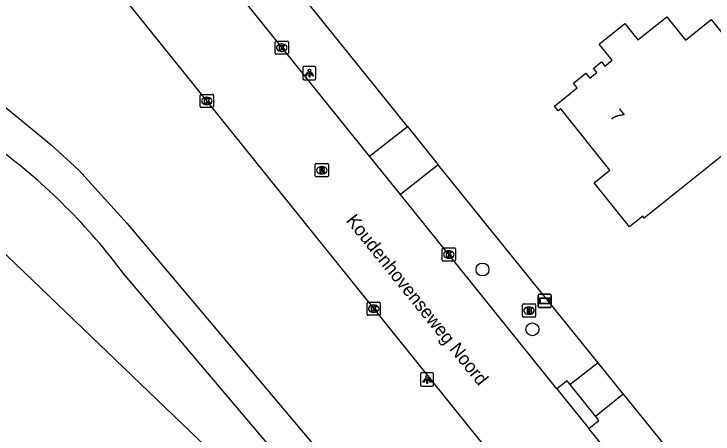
# Model space of a CAD drawing. Extents: x 162417 to 163721, y 384268 to 385416.
# Drawn here: x 163405.6 to 163458.5, y 384837.4 to 384869.2 of the extents above; entities that cross this region are included whole.
import ezdxf

# ---------------------------------------------------------------- set-up
doc = ezdxf.new("R2010")
doc.units = 0
for name, color, linetype in [('IMGEO_Berm_groen', 7, 'Continuous'), ('IMGEO_Boom', 7, 'Continuous'), ('IMGEO_Brandkraan', 7, 'Continuous'), ('IMGEO_Kolk', 7, 'Continuous'), ('IMGEO_Lichtpunt', 7, 'Continuous'), ('IMGEO_Loofbos', 7, 'Continuous'), ('IMGEO_Openbare_ruimte_label', 7, 'Continuous'), ('IMGEO_Pand', 7, 'Continuous'), ('IMGEO_Pand_nummerreeks', 7, 'Continuous'), ('IMGEO_Rijbaan_lokaal_gesloten', 7, 'Continuous'), ('IMGEO_Rioolput', 7, 'Continuous'), ('IMGEO_Verklikker', 7, 'Continuous'), ('IMGEO_Voetpad_open', 7, 'Continuous')]:
    doc.layers.add(name, color=color, linetype=linetype)

msp = doc.modelspace()

# ---------------------------------------------------------------- linework, layer by layer
at = {"layer": 'IMGEO_Berm_groen'}
for points in [[(163435.391, 384860.693), (163416.764, 384883.847)], [(163449.843, 384842.786), (163449.614, 384843.069), (163437.735, 384857.778)], [(163461.716, 384828.124), (163452.011, 384840.109), (163451.746, 384840.437)]]:
    msp.add_lwpolyline(points, dxfattribs=at)
at = {"layer": 'IMGEO_Boom'}
for centre in [(163441.083, 384849.86), (163444.862, 384845.327)]:
    msp.add_circle(centre, 0.489, dxfattribs=at)
at = {"layer": 'IMGEO_Brandkraan'}
for p, q in [((163444.106, 384846.323), (163444.106, 384847.175)), ((163444.181, 384847.249), (163445.033, 384847.249)), ((163444.594, 384847.029), (163444.619, 384847.029)), ((163445.107, 384847.175), (163445.107, 384846.323)), ((163444.617, 384846.469), (163444.592, 384846.469)), ((163445.033, 384846.249), (163444.181, 384846.249))]:
    msp.add_line(p, q, dxfattribs=at)
for points in [[(163444.106, 384846.323), (163444.106, 384847.175)], [(163444.181, 384847.249), (163445.033, 384847.249)], [(163445.107, 384847.175), (163445.107, 384846.323)], [(163444.454, 384846.949), (163444.454, 384846.549), (163444.667, 384846.549)], [(163444.685, 384846.949), (163444.454, 384846.949)], [(163444.633, 384846.868), (163444.579, 384846.868), (163444.579, 384846.792)], [(163444.579, 384846.792), (163444.632, 384846.792)], [(163444.641, 384846.716), (163444.579, 384846.716), (163444.579, 384846.635)], [(163444.579, 384846.635), (163444.641, 384846.635)], [(163445.033, 384846.249), (163444.181, 384846.249)]]:
    msp.add_lwpolyline(points, dxfattribs=at)
for centre, radius, start, end in [((163444.183, 384847.173), 0.0765, 91.552, 178.448), ((163444.183, 384847.173), 0.0765, 91.552, 178.448), ((163445.031, 384847.173), 0.0765, 1.552, 88.448), ((163445.031, 384847.173), 0.0765, 1.552, 88.448), ((163444.634, 384846.83), 0.0379, 267.8285, 90.9355), ((163444.642, 384846.675), 0.0404, 269.8759, 90.5077), ((163444.673, 384846.8), 0.251, 268.6676, 293.5347), ((163444.689, 384846.804), 0.145, 59.4692, 91.5367), ((163444.714, 384846.851), 0.0922, 285.5137, 58.1501), ((163444.719, 384846.659), 0.105, 301.3115, 78.989), ((163444.183, 384846.325), 0.0765, 181.552, 268.448), ((163444.183, 384846.325), 0.0765, 181.552, 268.448), ((163445.031, 384846.325), 0.0765, 271.552, 358.448), ((163445.031, 384846.325), 0.0765, 271.552, 358.448)]:
    msp.add_arc(centre, radius, start, end, dxfattribs=at)
for centre, major_axis, ratio, start_param, end_param in [((163444.593, 384846.749), (-0.387, 0.002), 0.722429, 4.712389, 7.853982), ((163444.618, 384846.749), (-0.39, 0.002), 0.717154, 1.570796, 4.712389)]:
    msp.add_ellipse(centre, major_axis=major_axis, ratio=ratio, start_param=start_param, end_param=end_param, dxfattribs=at)
at = {"layer": 'IMGEO_Kolk'}
for p, q in [((163425.375, 384866.238), (163425.375, 384867.09)), ((163425.45, 384867.164), (163426.302, 384867.164)), ((163426.376, 384867.09), (163426.376, 384866.238)), ((163425.863, 384866.944), (163425.888, 384866.944)), ((163426.302, 384866.164), (163425.45, 384866.164)), ((163425.886, 384866.384), (163425.861, 384866.384)), ((163419.7, 384862.2), (163419.7, 384863.052)), ((163419.775, 384863.126), (163420.627, 384863.126)), ((163420.188, 384862.906), (163420.213, 384862.906)), ((163420.701, 384863.052), (163420.701, 384862.2)), ((163420.211, 384862.346), (163420.186, 384862.346)), ((163420.627, 384862.126), (163419.775, 384862.126)), ((163438.029, 384850.568), (163438.029, 384851.42)), ((163438.104, 384851.494), (163438.956, 384851.494)), ((163438.517, 384851.274), (163438.542, 384851.274)), ((163439.03, 384851.42), (163439.03, 384850.568)), ((163438.54, 384850.714), (163438.515, 384850.714)), ((163438.956, 384850.494), (163438.104, 384850.494)), ((163432.342, 384846.464), (163432.342, 384847.316)), ((163432.417, 384847.39), (163433.269, 384847.39)), ((163432.83, 384847.17), (163432.855, 384847.17)), ((163433.343, 384847.316), (163433.343, 384846.464)), ((163432.853, 384846.61), (163432.828, 384846.61)), ((163433.269, 384846.39), (163432.417, 384846.39))]:
    msp.add_line(p, q, dxfattribs=at)
for points in [[(163425.375, 384866.238), (163425.375, 384867.09)], [(163425.45, 384867.164), (163426.302, 384867.164)], [(163426.376, 384867.09), (163426.376, 384866.238)], [(163425.696, 384866.864), (163425.819, 384866.864), (163425.819, 384866.713), (163425.949, 384866.864), (163426.113, 384866.864), (163425.967, 384866.713), (163426.12, 384866.464), (163425.968, 384866.464), (163425.883, 384866.628), (163425.819, 384866.561), (163425.819, 384866.464), (163425.696, 384866.464), (163425.696, 384866.864)], [(163426.302, 384866.164), (163425.45, 384866.164)], [(163419.7, 384862.2), (163419.7, 384863.052)], [(163419.775, 384863.126), (163420.627, 384863.126)], [(163420.701, 384863.052), (163420.701, 384862.2)], [(163420.021, 384862.826), (163420.144, 384862.826), (163420.144, 384862.675), (163420.274, 384862.826), (163420.438, 384862.826), (163420.292, 384862.675), (163420.445, 384862.426), (163420.293, 384862.426), (163420.208, 384862.59), (163420.144, 384862.523), (163420.144, 384862.426), (163420.021, 384862.426), (163420.021, 384862.826)], [(163420.627, 384862.126), (163419.775, 384862.126)], [(163438.029, 384850.568), (163438.029, 384851.42)], [(163438.104, 384851.494), (163438.956, 384851.494)], [(163438.35, 384851.194), (163438.473, 384851.194), (163438.473, 384851.043), (163438.603, 384851.194), (163438.767, 384851.194), (163438.621, 384851.043), (163438.774, 384850.794), (163438.622, 384850.794), (163438.537, 384850.958), (163438.473, 384850.891), (163438.473, 384850.794), (163438.35, 384850.794), (163438.35, 384851.194)], [(163439.03, 384851.42), (163439.03, 384850.568)], [(163438.956, 384850.494), (163438.104, 384850.494)], [(163432.342, 384846.464), (163432.342, 384847.316)], [(163432.417, 384847.39), (163433.269, 384847.39)], [(163432.663, 384847.09), (163432.786, 384847.09), (163432.786, 384846.939), (163432.916, 384847.09), (163433.08, 384847.09), (163432.934, 384846.939), (163433.087, 384846.69), (163432.935, 384846.69), (163432.85, 384846.854), (163432.786, 384846.787), (163432.786, 384846.69), (163432.663, 384846.69), (163432.663, 384847.09)], [(163433.343, 384847.316), (163433.343, 384846.464)], [(163433.269, 384846.39), (163432.417, 384846.39)]]:
    msp.add_lwpolyline(points, dxfattribs=at)
for centre, start, end in [((163425.452, 384867.088), 91.552, 178.448), ((163425.452, 384867.088), 91.552, 178.448), ((163426.3, 384867.088), 1.552, 88.448), ((163426.3, 384867.088), 1.552, 88.448), ((163425.452, 384866.24), 181.552, 268.448), ((163425.452, 384866.24), 181.552, 268.448), ((163426.3, 384866.24), 271.552, 358.448), ((163426.3, 384866.24), 271.552, 358.448), ((163419.777, 384863.05), 91.552, 178.448), ((163419.777, 384863.05), 91.552, 178.448), ((163420.625, 384863.05), 1.552, 88.448), ((163420.625, 384863.05), 1.552, 88.448), ((163419.777, 384862.202), 181.552, 268.448), ((163419.777, 384862.202), 181.552, 268.448), ((163420.625, 384862.202), 271.552, 358.448), ((163420.625, 384862.202), 271.552, 358.448), ((163438.106, 384851.418), 91.552, 178.448), ((163438.106, 384851.418), 91.552, 178.448), ((163438.954, 384851.418), 1.552, 88.448), ((163438.954, 384851.418), 1.552, 88.448), ((163438.106, 384850.57), 181.552, 268.448), ((163438.106, 384850.57), 181.552, 268.448), ((163438.954, 384850.57), 271.552, 358.448), ((163438.954, 384850.57), 271.552, 358.448), ((163432.419, 384847.314), 91.552, 178.448), ((163432.419, 384847.314), 91.552, 178.448), ((163433.267, 384847.314), 1.552, 88.448), ((163433.267, 384847.314), 1.552, 88.448), ((163432.419, 384846.466), 181.552, 268.448), ((163432.419, 384846.466), 181.552, 268.448), ((163433.267, 384846.466), 271.552, 358.448), ((163433.267, 384846.466), 271.552, 358.448)]:
    msp.add_arc(centre, 0.0765, start, end, dxfattribs=at)
for centre, major_axis, ratio, start_param, end_param in [((163425.862, 384866.664), (-0.387, 0.002), 0.722429, 4.712389, 7.853982), ((163425.887, 384866.664), (-0.39, 0.002), 0.717154, 1.570796, 4.712389), ((163420.187, 384862.626), (-0.387, 0.002), 0.722429, 4.712389, 7.853982), ((163420.212, 384862.626), (-0.39, 0.002), 0.717154, 1.570796, 4.712389), ((163438.516, 384850.994), (-0.387, 0.002), 0.722429, 4.712389, 7.853982), ((163438.541, 384850.994), (-0.39, 0.002), 0.717154, 1.570796, 4.712389), ((163432.829, 384846.89), (-0.387, 0.002), 0.722429, 4.712389, 7.853982), ((163432.854, 384846.89), (-0.39, 0.002), 0.717154, 1.570796, 4.712389)]:
    msp.add_ellipse(centre, major_axis=major_axis, ratio=ratio, start_param=start_param, end_param=end_param, dxfattribs=at)
at = {"layer": 'IMGEO_Lichtpunt'}
for p, q in [((163427.471, 384865.138), (163427.471, 384864.331)), ((163427.471, 384865.138), (163427.471, 384864.331)), ((163428.373, 384865.233), (163427.565, 384865.233)), ((163428.373, 384865.233), (163427.565, 384865.233)), ((163428.467, 384864.331), (163428.467, 384865.138)), ((163428.467, 384864.331), (163428.467, 384865.138)), ((163427.565, 384864.237), (163428.373, 384864.237)), ((163427.565, 384864.237), (163428.373, 384864.237)), ((163436.386, 384841.932), (163436.386, 384841.125)), ((163436.386, 384841.932), (163436.386, 384841.125)), ((163437.288, 384842.027), (163436.48, 384842.027)), ((163437.288, 384842.027), (163436.48, 384842.027)), ((163437.382, 384841.125), (163437.382, 384841.932)), ((163437.382, 384841.125), (163437.382, 384841.932)), ((163436.48, 384841.031), (163437.288, 384841.031)), ((163436.48, 384841.031), (163437.288, 384841.031))]:
    msp.add_line(p, q, dxfattribs=at)
for points in [[(163427.845, 384864.802), (163427.884, 384864.774), (163427.696, 384864.512), (163427.658, 384864.539), (163427.845, 384864.802)], [(163427.947, 384864.754), (163427.994, 384864.754), (163427.994, 384864.432), (163427.947, 384864.432), (163427.947, 384864.754)], [(163428.057, 384864.774), (163428.095, 384864.801), (163428.282, 384864.539), (163428.243, 384864.511), (163428.057, 384864.774)], [(163436.76, 384841.596), (163436.799, 384841.568), (163436.611, 384841.306), (163436.573, 384841.333), (163436.76, 384841.596)], [(163436.862, 384841.548), (163436.909, 384841.548), (163436.909, 384841.226), (163436.862, 384841.226), (163436.862, 384841.548)], [(163436.972, 384841.568), (163437.01, 384841.595), (163437.197, 384841.333), (163437.158, 384841.305), (163436.972, 384841.568)]]:
    msp.add_lwpolyline(points, dxfattribs=at)
for centre in [(163427.97, 384864.936), (163436.885, 384841.73)]:
    msp.add_circle(centre, 0.0994, dxfattribs=at)
for centre, start, end in [((163427.565, 384865.138), 90, 180), ((163427.565, 384865.138), 90, 180), ((163428.373, 384865.138), 0, 90), ((163428.373, 384865.138), 0, 90), ((163427.565, 384864.331), 180, 270), ((163427.565, 384864.331), 180, 270), ((163428.373, 384864.331), 270, 0), ((163428.373, 384864.331), 270, 360), ((163436.48, 384841.932), 90, 180), ((163436.48, 384841.932), 90, 180), ((163437.288, 384841.932), 0, 90), ((163437.288, 384841.932), 0, 90), ((163436.48, 384841.125), 180, 270), ((163436.48, 384841.125), 180, 270), ((163437.288, 384841.125), 270, 0), ((163437.288, 384841.125), 270, 360)]:
    msp.add_arc(centre, 0.0946, start, end, dxfattribs=at)
at = {"layer": 'IMGEO_Loofbos'}
msp.add_lwpolyline([(163449.552, 384814.496), (163444.744, 384812.832), (163371.736, 384882.911)], dxfattribs=at)
at = {"layer": 'IMGEO_Pand'}
for points in [[(163454.74, 384854.883), (163453.339, 384853.761), (163453.226, 384853.901), (163452.211, 384853.088), (163449.536, 384856.429), (163450.737, 384857.391), (163447.017, 384862.037), (163446.817, 384861.877), (163446.533, 384862.231), (163448.263, 384863.616), (163447.977, 384863.972), (163448.912, 384864.721), (163449.209, 384864.351), (163449.748, 384864.783), (163449.492, 384865.104), (163450.085, 384865.579), (163450.341, 384865.258), (163450.912, 384865.715), (163449.932, 384866.941), (163451.87, 384868.49), (163452.856, 384867.258), (163455.036, 384869.004), (163456.454, 384867.233), (163458.403, 384868.793), (163460.597, 384866.054)], [(163461.81, 384860.543), (163454.74, 384854.883)]]:
    msp.add_lwpolyline(points, dxfattribs=at)
at = {"layer": 'IMGEO_Rijbaan_lokaal_gesloten'}
for points in [[(163432.532, 384858.437), (163413.249, 384882.384)], [(163406.766, 384879.335), (163446.26, 384830.213), (163448.546, 384827.421)], [(163434.868, 384855.535), (163432.532, 384858.437)], [(163446.713, 384840.825), (163434.868, 384855.535)], [(163446.713, 384840.825), (163449.136, 384837.816)], [(163453.877, 384831.928), (163449.136, 384837.816)]]:
    msp.add_lwpolyline(points, dxfattribs=at)
at = {"layer": 'IMGEO_Rioolput'}
for p, q in [((163428.413, 384856.952), (163428.413, 384857.804)), ((163428.488, 384857.878), (163429.34, 384857.878)), ((163428.901, 384857.658), (163428.926, 384857.658)), ((163429.414, 384857.804), (163429.414, 384856.952)), ((163428.924, 384857.098), (163428.899, 384857.098)), ((163429.34, 384856.878), (163428.488, 384856.878))]:
    msp.add_line(p, q, dxfattribs=at)
for points in [[(163428.413, 384856.952), (163428.413, 384857.804)], [(163428.488, 384857.878), (163429.34, 384857.878)], [(163429.002, 384857.576), (163428.75, 384857.578), (163428.75, 384857.178)], [(163429.414, 384857.804), (163429.414, 384856.952)], [(163428.75, 384857.178), (163428.874, 384857.178), (163428.874, 384857.34), (163428.885, 384857.34)], [(163428.928, 384857.497), (163428.874, 384857.497), (163428.874, 384857.416)], [(163428.874, 384857.416), (163428.926, 384857.416)], [(163428.932, 384857.311), (163429.003, 384857.178), (163429.143, 384857.178), (163429.078, 384857.304)], [(163429.34, 384856.878), (163428.488, 384856.878)]]:
    msp.add_lwpolyline(points, dxfattribs=at)
for centre, radius, start, end in [((163428.49, 384857.802), 0.0765, 91.552, 178.448), ((163428.49, 384857.802), 0.0765, 91.552, 178.448), ((163429.001, 384857.466), 0.109, 350.3612, 89.416), ((163429.338, 384857.802), 0.0765, 1.552, 88.448), ((163429.338, 384857.802), 0.0765, 1.552, 88.448), ((163428.884, 384857.287), 0.0533, 26.0293, 88.6989), ((163428.91, 384857.605), 0.19, 274.7715, 282.9687), ((163428.934, 384857.401), 0.0964, 77.0061, 93.1865), ((163428.948, 384857.458), 0.0378, 276.6634, 79.6772), ((163428.999, 384857.466), 0.112, 277.5842, 350.9817), ((163428.983, 384857.251), 0.108, 29.5134, 73.7905), ((163428.49, 384856.954), 0.0765, 181.552, 268.448), ((163428.49, 384856.954), 0.0765, 181.552, 268.448), ((163429.338, 384856.954), 0.0765, 271.552, 358.448), ((163429.338, 384856.954), 0.0765, 271.552, 358.448)]:
    msp.add_arc(centre, radius, start, end, dxfattribs=at)
for centre, major_axis, ratio, start_param, end_param in [((163428.9, 384857.378), (-0.387, 0.002), 0.722429, 4.712389, 7.853982), ((163428.925, 384857.378), (-0.39, 0.002), 0.717154, 1.570796, 4.712389)]:
    msp.add_ellipse(centre, major_axis=major_axis, ratio=ratio, start_param=start_param, end_param=end_param, dxfattribs=at)
at = {"layer": 'IMGEO_Verklikker'}
for p, q in [((163445.295, 384847.088), (163445.295, 384847.888)), ((163445.295, 384847.888), (163445.295, 384847.088)), ((163445.395, 384847.988), (163446.185, 384847.988)), ((163446.185, 384847.988), (163445.395, 384847.988)), ((163446.285, 384847.888), (163446.285, 384847.088)), ((163446.285, 384847.088), (163446.285, 384847.888)), ((163446.185, 384846.988), (163445.395, 384846.988)), ((163445.395, 384846.988), (163446.185, 384846.988))]:
    msp.add_line(p, q, dxfattribs=at)
for points in [[(163445.396, 384847.72), (163446.184, 384847.72), (163446.184, 384847.256), (163445.396, 384847.256), (163445.396, 384847.72)], [(163445.461, 384847.655), (163445.461, 384847.321), (163446.119, 384847.321), (163446.119, 384847.655), (163445.461, 384847.655)]]:
    msp.add_lwpolyline(points, dxfattribs=at)
for centre, start, end in [((163445.395, 384847.888), 90, 180), ((163445.395, 384847.888), 90, 180), ((163446.185, 384847.888), 0, 90), ((163446.185, 384847.888), 360, 90), ((163445.395, 384847.088), 180, 270), ((163445.395, 384847.088), 180, 270), ((163446.185, 384847.088), 270, 0), ((163446.185, 384847.088), 270, 0)]:
    msp.add_arc(centre, 0.1, start, end, dxfattribs=at)
at = {"layer": 'IMGEO_Voetpad_open'}
for points in [[(163392.196, 384872.647), (163408.421, 384859.297), (163410.514, 384857.379), (163414.147, 384853.364), (163438.619, 384824.336), (163442.822, 384825.228), (163444.598, 384823.469)], [(163432.532, 384858.437), (163435.391, 384860.693)], [(163435.391, 384860.693), (163437.735, 384857.778)], [(163437.735, 384857.778), (163434.868, 384855.535)], [(163449.552, 384814.496), (163441.59, 384822.244), (163437.759, 384821.38), (163413.902, 384849.546)], [(163449.843, 384842.786), (163447.728, 384841.15)], [(163451.746, 384840.437), (163449.843, 384842.786)], [(163447.728, 384841.15), (163447.501, 384841.435), (163446.713, 384840.825)], [(163449.638, 384838.756), (163447.728, 384841.15)], [(163449.638, 384838.756), (163451.746, 384840.437)], [(163449.136, 384837.816), (163449.901, 384838.426), (163449.638, 384838.756)]]:
    msp.add_lwpolyline(points, dxfattribs=at)
msp.add_arc((163377.171, 384822.171), 45.81, 36.6968, 53.4969, dxfattribs=at)

# ---------------------------------------------------------------- texts
at = {"layer": 'IMGEO_Openbare_ruimte_label'}
msp.add_text('Koudenhovenseweg Noord', height=1, rotation=308.8298, dxfattribs=at).set_placement((163430.698, 384853.549))
at = {"layer": 'IMGEO_Pand_nummerreeks'}
msp.add_text('7', height=1, rotation=308.6839, dxfattribs=at).set_placement((163450.673, 384861.505))

doc.saveas('drawing.dxf')
